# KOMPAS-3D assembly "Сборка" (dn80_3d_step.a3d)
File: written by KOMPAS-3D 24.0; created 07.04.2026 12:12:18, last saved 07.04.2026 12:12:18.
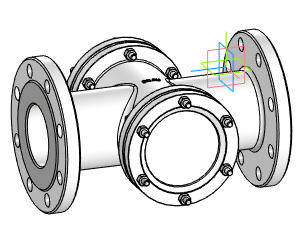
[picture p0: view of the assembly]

Document properties: Автор: Main; Полное имя файла: D:\DN.ru Аутсерс\Стекло смотровое DN.ru\Исходники\Стекло смотровое DN.ru SG2-34G-F тип В ГОСТ 21836-2021 Ду80 Ру16, углеродистая сталь, фланцевое\dn80_3d_step.a3d

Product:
- Component [detail]: Деталь  | qty 1  | Автор: Main; source file: ДетальДеталь.m3d
- Component [detail]: Стекло  | qty 2  | Автор: Main; source file: СтеклоСтекло.m3d
- Component [detail]: ANSI B18.2.4.2M - M8x1,25 - 13  | designation ANSI B18.2.4.2M - M8x1,25  | qty 1  | Автор: Main; source file: ANSI B18.2.4.2M - M8x1,25ANSI B18.2.4.2M - M8x1,25 - 13.m3d
- Component [detail]: ANSI B18.2.4.2M - M8x1,25 - 13  | designation ANSI B18.2.4.2M - M8x1,25  | qty 23  | Комментарий: Типы метрических   шестигранных гаек   2; Автор: Main; additional columns: Сталь, мягкая; source file: ANSI B18.2.4.2M - M8x1,25ANSI B18.2.4.2M - M8x1,25 - 13.m3d
- Part/product: Сборка

Referenced files in D:\DN.ru Аутсерс\Стекло смотровое DN.ru\Исходники\Стекло смотровое DN.ru SG2-34G-F тип В ГОСТ 21836-2021 Ду80 Ру16, углеродистая сталь, фланцевое\: ДетальДеталь.m3d, СтеклоСтекло.m3d, ANSI B18.2.4.2M - M8x1,25ANSI B18.2.4.2M - M8x1,25 - 13.m3d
